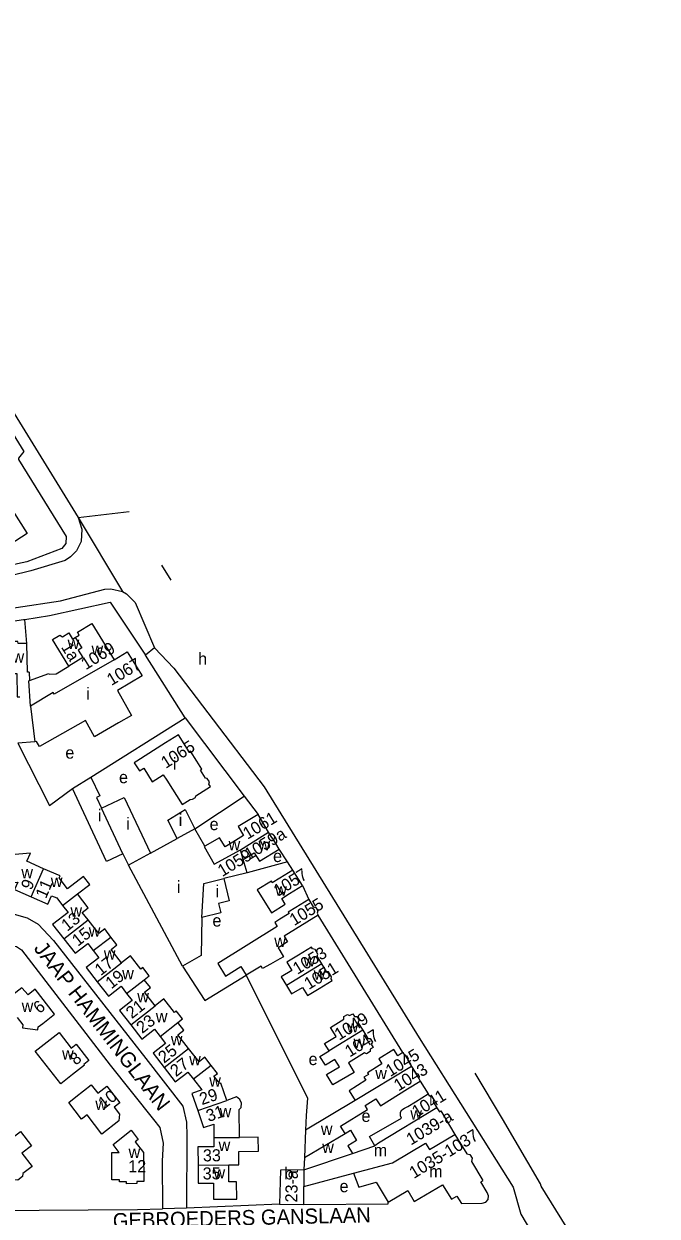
# Model space of a CAD drawing. Extents: x 156721 to 158827, y 386657 to 388950.
# Drawn here: x 158415.3 to 158625, y 387599.4 to 387994 of the extents above; entities that cross this region are included whole.
import ezdxf

# ---------------------------------------------------------------- set-up
doc = ezdxf.new("R2010")
doc.units = 0
for name, color, linetype in [('BLT_Basislijn', 7, 'Continuous'), ('BLT_Bebouwing', 7, 'Continuous'), ('BLT_Centroide', 7, 'Continuous'), ('BLT_Huisnummer', 7, 'Continuous'), ('BLT_Huisnummer_ tussenligend', 7, 'Continuous'), ('BLT_Huisnummer_reeks', 7, 'Continuous'), ('BLT_Onderverdeling_panden', 7, 'Continuous'), ('BLT_Straatnaam', 7, 'Continuous'), ('BLT_Vlakafsluiter', 7, 'Continuous')]:
    doc.layers.add(name, color=color, linetype=linetype)

msp = doc.modelspace()

# ---------------------------------------------------------------- linework, layer by layer
at = {"layer": 'BLT_Basislijn'}
for p, q in [((158416.28, 387788.96), (158415.64, 387796.93)), ((158468.67, 387764.4), (158455.54, 387785.04)), ((158464.95, 387780.83), (158476.22, 387766)), ((158437.44, 387744.74), (158468.67, 387764.4)), ((158468.67, 387764.4), (158488.26, 387738.46)), ((158413.27, 387756.01), (158423.79, 387735.32)), ((158423.79, 387735.32), (158431.4, 387740.93)), ((158471.92, 387727.61), (158488.26, 387738.46)), ((158488.26, 387738.46), (158492.87, 387732.36)), ((158502.55, 387716.71), (158499.86, 387720.85)), ((158502.55, 387716.71), (158489.18, 387713.04)), ((158504.33, 387713.98), (158502.55, 387716.71)), ((158507.51, 387708.82), (158509.64, 387704.21)), ((158540.82, 387653.57), (158512.78, 387699.07)), ((158546.58, 387644.16), (158549.22, 387639.91)), ((158508.8, 387632.74), (158508.57, 387627.93)), ((158469.13, 387602.11), (158461.22, 387601.86)), ((158499.89, 387603.36), (158469.13, 387602.11))]:
    msp.add_line(p, q, dxfattribs=at)
for points in [[(158087.6, 388388.98), (158120.58, 388335.72), (158121.32, 388334.13), (158168.5, 388258.11), (158180.9, 388237.55), (158193.49, 388217.63), (158243.23, 388136.8), (158258.3, 388113.07), (158338.44, 387984.38), (158433.27, 387830.65)], [(158403.65, 387871.1), (158415.3, 387852.51), (158413.44, 387850.27), (158413.49, 387849.88), (158429.25, 387824.31), (158429.19, 387822.01), (158427.85, 387820.41), (158416.25, 387815.94), (158403.36, 387813.19), (158396.41, 387812.46), (158380.57, 387811.75), (158375.47, 387811.87), (158359.02, 387813.54)], [(158433.27, 387830.65), (158434.5, 387826.74), (158434.3, 387822.71), (158432.7, 387819.57), (158430.7, 387817.62), (158428.91, 387816.45), (158417.63, 387813.01), (158410.83, 387811.39), (158391.76, 387808.28), (158384.35, 387808.16), (158363.48, 387808.67), (158344.47, 387810.76), (158305.12, 387817.62), (158302.66, 387818.59), (158300.22, 387821.39), (158299.92, 387822.82)], [(158255.41, 387816.62), (158350.63, 387802.1), (158376.41, 387799.92), (158393.79, 387799.68), (158412.74, 387800.86), (158427.37, 387803.09), (158442.12, 387806.96), (158444.04, 387807.08), (158447.96, 387806.2)], [(158464.11, 387809.92), (158460.99, 387814.92)], [(158447.96, 387806.2), (158449.22, 387805.4), (158452.12, 387802.47), (158458.5, 387787.52)], [(158415.64, 387796.93), (158423.73, 387798.18), (158443.85, 387802.68), (158455.54, 387785.04)], [(158371.87, 387795.58), (158376.59, 387795.15), (158396.53, 387794.82), (158407.91, 387795.83), (158415.19, 387796.86), (158415.64, 387796.93)], [(158458.5, 387787.52), (158455.54, 387785.04)], [(158476.22, 387766), (158494.81, 387741.54), (158546.18, 387658.49), (158577.36, 387609.01), (158579.85, 387600.13), (158594.83, 387574.97)], [(158374.47, 387696.79), (158408.63, 387699.47), (158412.06, 387699.32), (158416.39, 387698.12), (158419.97, 387696.03), (158425.04, 387690.66), (158455.7, 387651.62), (158467.94, 387635.79), (158469.13, 387630.57), (158469.28, 387625.94), (158469.13, 387602.11)], [(158341.75, 387684.53), (158406.99, 387688.87), (158409.83, 387689.02), (158412.81, 387688.72), (158414.45, 387687.52), (158443.84, 387649.45), (158458.24, 387631.46), (158460.33, 387628.78), (158461.37, 387623.55), (158461.08, 387617.73), (158461.22, 387601.86)], [(158467.86, 387682.18), (158475.21, 387670.82), (158488.93, 387679.18)], [(158488.93, 387679.18), (158509.18, 387638.52), (158508.8, 387632.74)], [(158625.03, 387546.43), (158622.39, 387550.67), (158608.54, 387573.98), (158586.62, 387609.33), (158586.4, 387610.13), (158573.82, 387631.65), (158564.76, 387646.72)], [(158508, 387603.31), (158535.98, 387603.51), (158535.98, 387604.1)], [(158394.96, 387601.28), (158396.6, 387601.27), (158403.89, 387601.3), (158452.92, 387601.61), (158461.22, 387601.86)]]:
    msp.add_lwpolyline(points, dxfattribs=at)
at = {"layer": 'BLT_Bebouwing'}
for p, q in [((158417.03, 387779.47), (158417.15, 387776.67)), ((158418.91, 387756.44), (158413.27, 387756.01)), ((158431.4, 387740.93), (158437.44, 387744.74)), ((158442.67, 387716.82), (158431.4, 387740.93)), ((158496.32, 387726.5), (158492.87, 387732.36)), ((158457.17, 387719.55), (158466.1, 387724.37)), ((158448.1, 387719.38), (158442.67, 387716.82)), ((158448.1, 387719.38), (158449.88, 387715.64)), ((158457.17, 387719.55), (158449.88, 387715.64)), ((158467.86, 387682.18), (158449.88, 387715.64)), ((158489.18, 387713.04), (158487.94, 387717.49)), ((158507.51, 387708.82), (158504.33, 387713.98)), ((158549.22, 387639.91), (158549.23, 387639.91)), ((158549.72, 387639.11), (158549.23, 387639.91)), ((158524.97, 387637.74), (158508.57, 387627.93)), ((158508.57, 387627.93), (158508.18, 387618.81)), ((158524.08, 387620.17), (158531.57, 387622.71)), ((158508.18, 387618.81), (158508.05, 387614.74)), ((158499.89, 387603.36), (158508, 387603.31))]:
    msp.add_line(p, q, dxfattribs=at)
for points in [[(158400.4, 387830.17), (158399.65, 387831.35), (158398, 387833.95), (158407.14, 387839.78), (158416.33, 387825.35), (158407.21, 387819.52), (158405.62, 387822)], [(158432.27, 387790.96), (158433.57, 387791.76), (158432.99, 387792.7), (158437.79, 387795.6), (158445.22, 387783.56)], [(158416.28, 387788.96), (158413.34, 387788.9), (158413.31, 387789.6), (158412.17, 387789.61), (158411.56, 387790.38), (158410.77, 387790.36), (158409.99, 387790.35), (158409.42, 387789.57), (158408.31, 387789.53), (158408.42, 387779.01), (158412.92, 387779.06), (158413, 387771.29), (158413.93, 387771.27)], [(158430.12, 387781.46), (158424.7, 387790.23), (158427.16, 387791.75), (158428.12, 387791.15), (158430.18, 387792.43), (158431.42, 387790.43), (158432.27, 387790.96)], [(158417.03, 387779.47), (158416.43, 387779.48), (158416.28, 387788.96)], [(158445.22, 387783.56), (158449.51, 387786.21), (158454.42, 387778.26), (158446.23, 387773.36), (158450.96, 387765.15), (158446.63, 387762.65), (158438.72, 387758.09), (158435.65, 387763.45), (158420.45, 387754.84), (158419.46, 387756.49), (158418.91, 387756.44)], [(158417.15, 387776.67), (158423.59, 387778.97), (158423.64, 387778.84), (158425.96, 387778.89), (158430.12, 387781.46)], [(158472.56, 387750), (158470.45, 387753.35), (158470, 387753.07), (158466.45, 387758.69), (158462.23, 387756.02), (158452.69, 387750), (158451.84, 387749.47), (158453.54, 387746.79), (158454.99, 387747.7), (158457.82, 387743.21), (158461.43, 387745.49), (158462.57, 387743.69)], [(158462.57, 387743.69), (158467.65, 387735.64), (158470.35, 387737.35), (158471.12, 387737.39), (158472.09, 387738), (158472.22, 387738.57), (158477.06, 387741.63), (158476.55, 387742.43), (158476.71, 387743.12), (158475.96, 387744.31), (158475.4, 387744.43), (158473.73, 387747.07), (158474.22, 387747.38), (158472.56, 387750)], [(158437.44, 387744.74), (158440.44, 387738.48), (158439.33, 387737.94), (158440.97, 387734.47)], [(158440.97, 387734.47), (158448.44, 387738), (158457.17, 387719.55)], [(158466.1, 387724.37), (158462.96, 387730.43), (158468.69, 387734), (158471.92, 387727.61)], [(158492.87, 387732.36), (158486.26, 387728.35), (158488.04, 387725.41), (158484.46, 387723.23)], [(158475.17, 387721.89), (158471.92, 387727.61)], [(158499.86, 387720.85), (158497.59, 387724.59), (158497.49, 387724.53), (158496.32, 387726.5)], [(158484.46, 387723.23), (158481.93, 387721.7), (158480.11, 387724.69), (158475.17, 387721.89)], [(158421.79, 387714.43), (158416.29, 387716.87), (158417.46, 387719.52), (158408.5, 387718.82), (158408.01, 387717.44)], [(158487.94, 387717.49), (158491.6, 387719.71), (158493.31, 387716.88), (158499.86, 387720.85)], [(158432.99, 387706.08), (158437.07, 387709.24), (158435.05, 387711.85), (158429.76, 387707.76), (158426.97, 387711.37), (158427.26, 387712.01), (158421.79, 387714.43)], [(158481.45, 387711.13), (158483.28, 387703.74), (158479.72, 387702.86), (158480.47, 387699.82), (158474.27, 387698.28)], [(158489.18, 387713.04), (158481.45, 387711.13)], [(158504.33, 387713.98), (158500, 387711.31), (158497.53, 387709.79), (158497.24, 387710.26), (158492.59, 387707.39), (158497.27, 387699.81), (158501.87, 387702.66), (158500.69, 387704.61), (158503.26, 387706.2), (158507.51, 387708.82)], [(158408.66, 387709.62), (158413.26, 387709.98), (158412.17, 387707.53), (158417.67, 387705.1)], [(158417.67, 387705.1), (158423.17, 387702.68), (158424.38, 387705.47), (158426.14, 387704.73), (158428.07, 387702.25)], [(158436.55, 387697.47), (158434.63, 387699.94), (158436.59, 387701.47), (158432.99, 387706.08)], [(158509.64, 387704.21), (158505.38, 387701.6), (158502.84, 387700.04), (158503.12, 387699.6), (158500, 387697.69), (158498.34, 387696.67), (158499.21, 387695.26), (158479.48, 387683.03)], [(158509.64, 387704.21), (158511.11, 387701.8), (158511.97, 387701.6), (158512.63, 387700.52), (158512.42, 387699.65), (158512.78, 387699.07)], [(158428.07, 387702.25), (158429.9, 387699.89), (158424.81, 387695.9), (158428.51, 387691.18)], [(158512.78, 387699.07), (158501.44, 387692.12), (158502.63, 387690.17), (158500, 387688.56), (158499.46, 387688.23), (158500, 387687.36), (158501.29, 387685.26), (158500, 387684.55), (158496.91, 387682.84), (158494.34, 387681.42), (158493.86, 387682.21), (158488.93, 387679.18)], [(158444.12, 387691.81), (158442.04, 387694.47), (158440.09, 387692.95), (158436.55, 387697.47)], [(158474.27, 387698.28), (158473.99, 387685.69), (158467.86, 387682.18)], [(158428.51, 387691.18), (158432.21, 387686.45), (158436.42, 387689.68), (158438.24, 387687.3)], [(158447.62, 387683.28), (158444.15, 387687.72), (158446.11, 387689.25), (158444.12, 387691.81)], [(158438.24, 387687.3), (158440.06, 387684.93), (158435.89, 387681.72), (158439.58, 387676.99)], [(158513.98, 387682.93), (158512.46, 387685.43), (158512.64, 387686.13), (158511.72, 387687.66), (158510.91, 387687.86), (158510.56, 387688.43), (158506.28, 387685.84), (158502.36, 387683.47), (158504.03, 387680.72), (158500.54, 387678.61), (158502.23, 387675.82)], [(158455.15, 387677.69), (158456.82, 387679), (158454.7, 387681.7), (158454.03, 387681.18), (158450.63, 387685.54), (158447.62, 387683.28)], [(158479.48, 387683.03), (158482.03, 387678.87), (158487.18, 387682.03), (158488.93, 387679.18)], [(158502.23, 387675.82), (158503.95, 387672.98), (158507.55, 387675.15), (158509.18, 387672.45), (158513.11, 387674.82), (158517.38, 387677.41), (158517.01, 387678.02), (158517.17, 387678.67), (158516.21, 387680.25), (158515.49, 387680.43), (158513.98, 387682.93)], [(158439.58, 387676.99), (158443.28, 387672.27), (158447.45, 387675.51), (158449.29, 387673.14)], [(158458.71, 387669.09), (158455.22, 387673.55), (158457.18, 387675.09), (158455.15, 387677.69)], [(158421.52, 387663.23), (158425.44, 387666.33), (158419.04, 387674.51), (158416.71, 387672.71), (158414.59, 387674.98), (158410.62, 387671.94), (158408.29, 387670.16)], [(158449.29, 387673.14), (158451.13, 387670.78), (158446.96, 387667.54), (158450.66, 387662.8)], [(158466.23, 387663.52), (158467.81, 387664.75), (158465.76, 387667.37), (158465.12, 387666.87), (158461.63, 387671.35), (158458.71, 387669.09)], [(158413.03, 387665.23), (158414.95, 387662.77), (158414.83, 387661.78), (158419.9, 387661.15), (158420.01, 387662.04), (158421.52, 387663.23)], [(158469.82, 387654.89), (158466.29, 387659.4), (158468.26, 387660.94), (158466.23, 387663.52)], [(158516.34, 387654.13), (158514.87, 387656.52), (158518.72, 387658.9), (158516.86, 387661.92), (158521.29, 387664.65), (158521.27, 387665.48), (158522.42, 387666.19), (158523.15, 387665.8), (158524.19, 387666.44), (158524.8, 387665.46), (158525.56, 387665.49), (158526.32, 387664.25), (158525.93, 387663.52), (158527.51, 387660.97)], [(158431.41, 387646.3), (158427.46, 387643.22), (158419.05, 387654.03), (158422.99, 387657.13), (158426.92, 387660.23), (158430.98, 387655.04), (158432.61, 387656.31), (158436.81, 387650.9), (158435.17, 387649.61), (158435.35, 387649.38), (158431.41, 387646.3)], [(158450.66, 387662.8), (158454.37, 387658.06), (158458.51, 387661.31), (158460.38, 387658.92)], [(158527.51, 387660.97), (158529.2, 387658.22), (158529.98, 387658.24), (158530.73, 387657.03), (158530.35, 387656.33), (158530.98, 387655.3), (158530, 387654.7), (158530.02, 387653.88), (158528.77, 387653.1), (158528.09, 387653.47), (158522.77, 387650.19), (158524.72, 387646.93), (158517.64, 387642.84), (158515.55, 387646.28), (158519.81, 387648.87), (158518.32, 387651.28), (158515.18, 387649.35), (158513.35, 387652.28), (158516.34, 387654.13)], [(158460.38, 387658.92), (158462.2, 387656.61), (158458.07, 387653.36), (158461.75, 387648.62)], [(158477.33, 387649.34), (158475.26, 387652), (158473.29, 387650.46), (158469.82, 387654.89)], [(158540.82, 387653.57), (158539.1, 387652.5), (158537.79, 387654.61), (158532.79, 387651.51), (158533.82, 387649.85), (158529.04, 387646.89), (158529.38, 387646.33), (158527.92, 387645.42)], [(158540.82, 387653.57), (158541.37, 387652.67), (158542.06, 387652.5), (158542.6, 387651.63), (158542.44, 387650.96), (158543.69, 387648.94)], [(158461.75, 387648.62), (158465.43, 387643.88), (158469.57, 387647.12), (158471.44, 387644.73)], [(158482.48, 387637.76), (158480.52, 387643.41), (158480.15, 387643.29), (158478.22, 387645.77), (158479.41, 387646.69), (158477.33, 387649.34)], [(158543.69, 387648.94), (158545.08, 387646.71), (158545.71, 387646.56), (158546.22, 387645.74), (158546.05, 387645.02), (158546.58, 387644.16)], [(158471.44, 387644.73), (158474.2, 387641.22), (158470.87, 387640.07), (158472.85, 387634.4)], [(158521.67, 387626.79), (158520.15, 387629.23), (158529.06, 387634.75), (158528.26, 387636.05), (158531.89, 387638.3), (158533.34, 387635.96), (158542.33, 387641.53), (158546.58, 387644.16)], [(158527.92, 387645.42), (158528.56, 387644.4), (158522.96, 387640.93), (158524.97, 387637.74)], [(158441.12, 387626.61), (158436.21, 387632.94), (158434.4, 387631.53), (158434.4, 387631.53), (158430.11, 387637.06), (158432.47, 387638.9), (158437.54, 387642.87), (158439.72, 387640.11), (158442.74, 387642.48), (158447.05, 387636.95), (158445.14, 387635.46), (158446.96, 387633.14), (158446.71, 387630.98), (158441.12, 387626.61)], [(158531.57, 387622.71), (158529.8, 387625.79), (158540.33, 387631.84), (158539.98, 387632.64), (158539.97, 387633.83), (158540.49, 387634.65), (158541.29, 387635.21), (158542.45, 387635.74), (158544.97, 387637.29), (158549.22, 387639.91)], [(158486.66, 387625.48), (158486.6, 387634.73), (158487.24, 387635.43), (158487.31, 387636.8), (158486.76, 387638.08), (158485.75, 387638.88), (158482.48, 387637.76)], [(158549.72, 387639.11), (158550.39, 387638.95), (158551.04, 387637.9), (158550.89, 387637.27), (158552.09, 387635.31)], [(158472.85, 387634.4), (158474.82, 387628.73), (158478.15, 387629.89), (158478.18, 387625.42)], [(158552.09, 387635.31), (158552.89, 387634), (158553.33, 387634.27), (158558.06, 387626.48)], [(158453.17, 387624.83), (158452.12, 387623.99), (158454.91, 387620.46), (158455.02, 387610.89), (158452.69, 387610.85), (158452.69, 387610.19), (158449.24, 387610.18), (158449.24, 387610.84), (158446.92, 387610.83), (158446.92, 387611.41), (158444.45, 387611.4), (158444.39, 387620.5), (158446.85, 387620.51), (158444.84, 387623.18), (158450.8, 387627.86), (158453.17, 387624.83)], [(158521.67, 387626.79), (158523.46, 387627.86), (158525.45, 387624.46), (158522.6, 387622.74), (158524.08, 387620.17)], [(158409.22, 387609.05), (158407.83, 387610.84), (158406.73, 387611.03), (158405.49, 387612.62), (158405.63, 387613.6), (158404.18, 387615.52), (158409.86, 387619.98), (158407.81, 387622.57), (158414.14, 387627.49), (158417.83, 387622.75), (158414.59, 387620.23), (158417.97, 387615.88), (158414.95, 387613.52), (158414.81, 387612.51), (158413.25, 387611.3), (158412.23, 387611.4), (158409.22, 387609.05)], [(158478.18, 387625.42), (158478.2, 387622.4), (158472.93, 387622.36), (158472.98, 387616.36)], [(158483.17, 387616.44), (158486.49, 387616.46), (158486.45, 387620.86), (158492.94, 387620.92), (158492.9, 387625.53), (158486.66, 387625.48)], [(158558.06, 387626.48), (158561.95, 387620.11)], [(158561.95, 387620.11), (158563, 387619.85), (158563.78, 387618.57), (158563.53, 387617.53), (158567.33, 387611.25)], [(158472.98, 387616.36), (158473.02, 387610.36), (158478.03, 387610.4), (158478.07, 387605.05), (158485.78, 387605.11), (158485.74, 387610.77), (158483.2, 387610.75), (158483.17, 387616.44)], [(158508.05, 387614.74), (158500.26, 387614.62), (158499.89, 387603.36)], [(158508.04, 387609.25), (158524.4, 387613.69)], [(158524.4, 387613.69), (158526.17, 387609.01), (158532, 387610.67)], [(158508, 387603.31), (158508.04, 387609.25)], [(158532, 387610.67), (158535.98, 387604.1)], [(158542.46, 387607.91), (158544.59, 387604.29), (158553.94, 387609.79), (158556.86, 387605.01), (158558.64, 387606.09), (158560.27, 387603.61), (158567.07, 387603.78), (158568.23, 387604.05), (158569.07, 387604.93), (158569.13, 387606.17), (158568.74, 387607.29), (158566.6, 387610.81), (158567.33, 387611.25)], [(158535.98, 387604.1), (158542.46, 387607.91)]]:
    msp.add_lwpolyline(points, dxfattribs=at)
at = {"layer": 'BLT_Onderverdeling_panden'}
for p, q in [((158417.15, 387776.67), (158416.94, 387776.59)), ((158417.5, 387768.18), (158416.94, 387776.59)), ((158417.5, 387768.18), (158418.91, 387756.44)), ((158448.1, 387719.38), (158440.97, 387734.47)), ((158471.92, 387727.61), (158466.1, 387724.37)), ((158487.94, 387717.49), (158487.04, 387720.68)), ((158417.67, 387705.1), (158421.79, 387714.43)), ((158428.07, 387702.25), (158432.99, 387706.08)), ((158428.51, 387691.18), (158436.55, 387697.47)), ((158438.24, 387687.3), (158444.12, 387691.81)), ((158439.58, 387676.99), (158447.62, 387683.28)), ((158513.98, 387682.93), (158502.23, 387675.82)), ((158449.29, 387673.14), (158455.15, 387677.69)), ((158450.66, 387662.8), (158458.71, 387669.09)), ((158460.38, 387658.92), (158466.23, 387663.52)), ((158527.51, 387660.97), (158516.34, 387654.13)), ((158461.75, 387648.62), (158469.82, 387654.89)), ((158477.33, 387649.34), (158471.44, 387644.73)), ((158543.69, 387648.94), (158524.97, 387637.74)), ((158472.85, 387634.4), (158482.48, 387637.76)), ((158478.18, 387625.42), (158486.66, 387625.48)), ((158508.05, 387614.74), (158524.08, 387620.17)), ((158472.98, 387616.36), (158483.17, 387616.44)), ((158508.05, 387614.74), (158508.04, 387609.25))]:
    msp.add_line(p, q, dxfattribs=at)
for points in [[(158432.27, 387790.96), (158434.45, 387787.5), (158433.24, 387786.74), (158434.81, 387784.27), (158430.12, 387781.46)], [(158445.22, 387783.56), (158425.28, 387772.22), (158425, 387772.69), (158417.5, 387768.18)], [(158487.04, 387720.68), (158496.32, 387726.5)], [(158475.17, 387721.89), (158475, 387721.79), (158478.27, 387715.93), (158487.04, 387720.68)], [(158474.27, 387698.28), (158474.93, 387709.52), (158481.45, 387711.13)], [(158552.09, 387635.31), (158532.74, 387623.56), (158531.57, 387622.71)], [(158508.18, 387618.81), (158521.67, 387626.79)], [(158524.4, 387613.69), (158537.34, 387617.13), (158548.32, 387623.64), (158549.6, 387621.49), (158558.06, 387626.48)]]:
    msp.add_lwpolyline(points, dxfattribs=at)
at = {"layer": 'BLT_Vlakafsluiter'}
for p, q in [((158433.27, 387830.65), (158450.11, 387832.63)), ((158433.27, 387830.65), (158447.96, 387806.2)), ((158464.95, 387780.83), (158458.5, 387787.52))]:
    msp.add_line(p, q, dxfattribs=at)

# ---------------------------------------------------------------- texts
at = {"layer": 'BLT_Centroide'}
for s, p in [('w', (158429.77, 387787.11)), ('w', (158411.53, 387782.61)), ('w', (158437.69, 387785.16)), ('h', (158472.97, 387781.89)), ('i', (158435.91, 387770.38)), ('e', (158429.01, 387750.84)), ('i', (158464.61, 387747.16)), ('e', (158446.79, 387742.71)), ('i', (158439.75, 387730.05)), ('i', (158449.19, 387727.34)), ('i', (158466.56, 387728.59)), ('e', (158476.8, 387727.19)), ('w', (158483.08, 387720.48)), ('w', (158492.99, 387720.48)), ('e', (158497.81, 387716.62)), ('w', (158414.43, 387711.25)), ('w', (158424.2, 387708.34)), ('i', (158465.92, 387706.43)), ('i', (158478.77, 387704.94)), ('w', (158498.52, 387705.5)), ('w', (158430.7, 387698.59)), ('w', (158436.76, 387691.97)), ('e', (158477.73, 387695.28)), ('w', (158498.19, 387688.56)), ('w', (158441.75, 387684.34)), ('w', (158507.91, 387682.12)), ('w', (158447.83, 387677.78)), ('w', (158511.27, 387677.69)), ('w', (158452.83, 387670.2)), ('w', (158414.55, 387667.03)), ('w', (158458.98, 387663.56)), ('w', (158522.21, 387660.22)), ('w', (158463.95, 387656.02)), ('w', (158524.45, 387655.09)), ('w', (158427.92, 387651.27)), ('w', (158470.02, 387649.38)), ('e', (158509.57, 387649.43)), ('w', (158531.65, 387644.78)), ('w', (158476.67, 387642.28)), ('w', (158438.95, 387634.56)), ('w', (158480.12, 387632.16)), ('e', (158527.1, 387630.62)), ('w', (158543.27, 387631.41)), ('w', (158513.64, 387626.32)), ('w', (158479.77, 387620.97)), ('w', (158449.94, 387618.69)), ('w', (158514.09, 387620.34)), ('m', (158531.16, 387619.25)), ('w', (158478.1, 387611.91)), ('b', (158501.53, 387611.59)), ('m', (158549.49, 387612.25)), ('e', (158519.84, 387607.36))]:
    msp.add_text(s, height=4, dxfattribs=at).set_placement(p)
at = {"layer": 'BLT_Huisnummer'}
for s, rotation, p in [('1a', 301.712, (158427.48, 387787.75)), ('1069', 31.7097, (158435.78, 387780.07)), ('1067', 30.9071, (158444.26, 387774.87)), ('1065', 32.2838, (158462.28, 387747.44)), ('1061', 31.2484, (158489.34, 387723.97)), ('1059a', 31.2459, (158489.84, 387717.15)), ('1059', 31.2459, (158480.99, 387711.63)), ('1057', 31.6977, (158499.53, 387705.13)), ('11', 66.5517, (158422.57, 387704.28)), ('1055', 31.4957, (158504.8, 387695.39)), ('15', 38.1368, (158433.18, 387688.55)), ('1053', 31.1684, (158505.87, 387679.29)), ('1051', 31.1623, (158509.63, 387674.26)), ('19', 38.1368, (158444.24, 387674.45)), ('6', 38.2982, (158420.37, 387666.26)), ('23', 38.1368, (158454.48, 387659.69)), ('1049', 31.682, (158519.7, 387657.48)), ('1047', 31.6898, (158523.17, 387651.89)), ('8', 37.9635, (158432.41, 387649.18)), ('27', 38.1368, (158465.67, 387645.36)), ('1045', 31.7732, (158536.63, 387645.42)), ('1043', 31.7794, (158539.35, 387640.65)), ('10', 37.9813, (158441.83, 387634.71)), ('1041', 31.6078, (158545.38, 387631.98)), ('31', 19.0681, (158476.45, 387630.58)), ('12', 0.2493, (158449.86, 387613.95)), ('35', 0.3918, (158474.51, 387611.57))]:
    msp.add_text(s, height=4, rotation=rotation, dxfattribs=at).set_placement(p)
at = {"layer": 'BLT_Huisnummer_ tussenligend'}
for s, rotation, p in [('9', 66.1613, (158417.74, 387707.09)), ('13', 38.1368, (158429.62, 387693.51)), ('17', 38.1368, (158440.7, 387678.8)), ('21', 38.1368, (158451.03, 387664.59)), ('25', 38.1368, (158461.72, 387649.85)), ('29', 19.0681, (158474.25, 387636.14)), ('33', 0.3918, (158474.58, 387617.55))]:
    msp.add_text(s, height=4, rotation=rotation, dxfattribs=at).set_placement(p)
at = {"layer": 'BLT_Huisnummer_reeks'}
for s, rotation, p in [('1039-a', 30.8909, (158543.45, 387622.77)), ('1035-1037', 31.4104, (158544.46, 387611.72)), ('23-a', 88.7612, (158505.82, 387603.93))]:
    msp.add_text(s, height=4, rotation=rotation, dxfattribs=at).set_placement(p)
at = {"layer": 'BLT_Straatnaam'}
for s, rotation, p in [('JAAP HAMMINGLAAN', 307.6709, (158418.34, 387687.95)), ('GEBROEDERS GANSLAAN', 1.3544, (158444.79, 387595.4))]:
    msp.add_text(s, height=5, rotation=rotation, dxfattribs=at).set_placement(p)

doc.saveas('drawing.dxf')
